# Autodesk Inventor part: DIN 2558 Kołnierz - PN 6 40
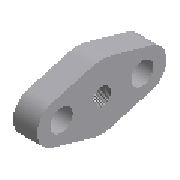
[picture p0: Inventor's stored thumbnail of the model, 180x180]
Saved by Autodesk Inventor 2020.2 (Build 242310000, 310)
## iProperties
Manager: www.cadconsulting.pl
Company: Fabian Stasiak CAD Consulting
IsCustomPart: 0
NAME: PIPING: DIN 2558 Flange - PN 6
DATA: <meta><inlinegroups number="1" deflen="1.2"></inlinegroups><connections number="2"></connections><angles><a>3.14159265358979</a></angles></meta>
Created: 2014-02
Part Number: DIN 2558 Kołnierz - PN 6 40
Material: Stal
Description: Kołnierz
Document SubType Name: Modeling
Standard: DIN 2558
Designer: F.Stasiak
Standards Organization: DIN
Language: pl-PL
Size Designation: 40
Categories: <MemberInstance><Categories><Category DisplayName="Rury cienko- i grubościenne" InternalName="4347fa0f-2144-441d-94cd-e3e15c92b736" Mnemonic="TUBEANDPIPE"><Cate
Density: 1 g/cm^3
Appearance: Płyta
Catalog Web Link: www.expertbooks.pl
Author: F.Stasiak
Subject: Zbiór ćwiczeń. Autodesk Inventor 2020. Kurs Professional
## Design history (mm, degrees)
sketch "Sketch1"
  geometry: L1 (0, 0)-(0, 66); L2 (0, 0)-(0, -66); L3 (-20.899, 54.72)-(-39.708, 26.067); L4 (20.899, 54.72)-(39.708, 26.067); L5 (-20.899, -54.72)-(-39.708, -26.067); L6 (20.899, -54.72)-(39.708, -26.067); L7 (0, 0)-(47.5, 0); L8 (0, 0)-(-47.5, 0); C1 r 22.422 at (0, 0); C2 r 5.5 at (0, 50); C3 r 5.5 at (0, -50); A1 r 25 centre (0, 41) between (20.899, 54.72) and (-20.899, 54.72); A2 r 25 centre (0, -41) between (-20.899, -54.72) and (20.899, -54.72); A3 r 47.5 centre (0, 0) between (39.708, -26.067) and (39.708, 26.067); A4 r 47.5 centre (0, 0) between (-39.708, 26.067) and (-39.708, -26.067); 1 further point
  constraints: 16 end point, 12 point on circle, 8 tangent, 7 centre point, 4 point on line, 2 collinear, 1 coincident, 1 perpendicular, 1 vertical
  dimensions: "d0" = 44.845 diameter of C1 (= MD); "d1" = 11 diameter of C2 (= d2); "d3" = 11 diameter of C3 (= d2); "d4" = 66 vertical distance of L7.end L1.end (= 0.5 x A); "d5" = 66 vertical distance of L2.end L7.end (= 0.5 x A); "d6" = 50 vertical distance of L7.end C2.centre (= 0.5 x k); "d7" = 50 vertical distance of C3.centre L7.end (= 0.5 x k); "d8" = 25 radius of A1 (= r); "d9" = 25 radius of A2 (= r); "d10" = 47.5 radius of A4 (= R); "d11" = 47.5 radius of A3 (= R)
extrude "Extrusion1" new body sketch "Sketch1" distance "d12" = 16 (= b); taper "d13" = 0 deg
workaxis "Work Axis4"
workpoint "Work Point5"
workaxis "Work Axis5"
workpoint "Work Point6"
workpoint "Work Point7"
body "Solid1"
feature "Gwint1" dims "d17" = 10, "d18" = 0
other parameters: "A" = 132 [user parameter; used in 2 equation terms], "R" = 47.5 [user parameter; used in 2 equation terms], "r" = 25 [user parameter; used in 2 equation terms], "d2" = 11 [user parameter; used in 2 equation terms], "b" = 16 [user parameter; used in 1 equation term], "MD" = 44.845 [user parameter; used in 1 equation term]
